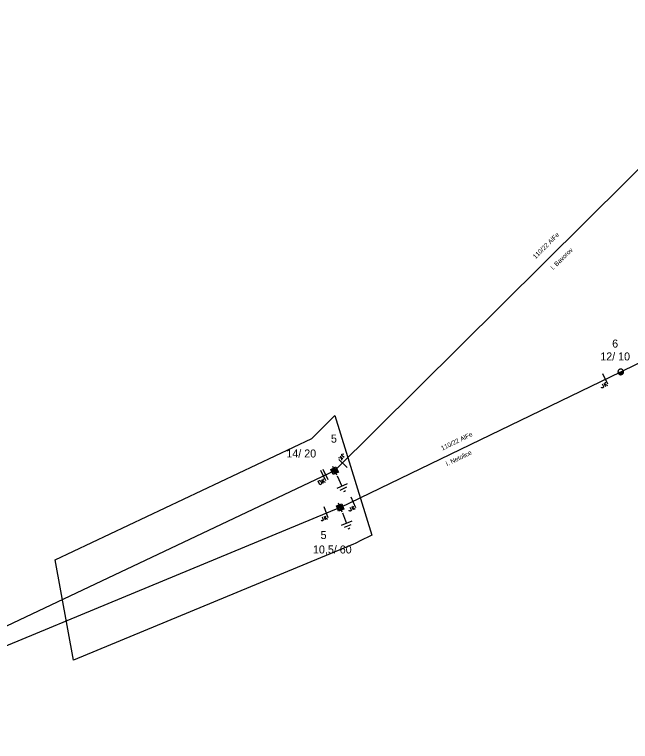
# Model space of a CAD drawing. Extents: x -788491 to -785797, y -1154753 to -1152002.
# Drawn here: x -787286.3 to -787151.7, y -1153654.2 to -1153495.3 of the extents above; entities that cross this region are included whole.
import ezdxf

# ---------------------------------------------------------------- set-up
doc = ezdxf.new("R2010")
doc.units = 0
for name, color, linetype in [('Vrstva 1', 7, 'Continuous'), ('Vrstva 13', 7, 'Continuous'), ('Vrstva 14', 7, 'Continuous'), ('Vrstva 15', 7, 'Continuous'), ('Vrstva 18', 7, 'Continuous'), ('Vrstva 2', 7, 'Continuous'), ('Vrstva 3', 7, 'Continuous'), ('Vrstva 35', 7, 'Continuous'), ('Vrstva 49', 7, 'Continuous')]:
    doc.layers.add(name, color=color, linetype=linetype)

# ---------------------------------------------------------------- blocks, each defined once
blk = doc.blocks.new('VN850')
at = {"layer": 'Vrstva 15'}
for points in [[(-0.56, 1.43), (-0.56, -1.07)], [(-0.01, 1.43), (-0.01, -1.07)], [(-2.09, -0.54), (-1.78, -0.54)], [(-2.09, -1.41), (-2.09, -0.54)], [(-1.78, -1.41), (-2.09, -1.41)], [(-1.78, -0.54), (-1.66, -0.6)], [(-1.67, -1.35), (-1.78, -1.41)], [(-1.59, -1.2), (-1.67, -1.35)], [(-1.66, -0.6), (-1.59, -0.75)], [(-1.59, -0.75), (-1.55, -0.96)], [(-1.55, -0.96), (-1.59, -1.2)], [(-1.26, -0.54), (-1.26, -1.41)], [(-0.85, -0.54), (-1.26, -1.09)], [(-1.13, -0.92), (-0.77, -1.41)]]:
    blk.add_lwpolyline(points, dxfattribs=at)
blk = doc.blocks.new('VN840')
at = {"layer": 'Vrstva 15'}
for points in [[(-0.01, 1.41), (-0.01, -1.09)], [(-1.51, -1.24), (-1.51, -1.15)], [(-1.48, -1.35), (-1.51, -1.24)], [(-1.33, -1.42), (-1.48, -1.35)], [(-1.27, -1.42), (-1.33, -1.42)], [(-1.13, -1.35), (-1.27, -1.42)], [(-1.09, -1.24), (-1.13, -1.35)], [(-1.09, -0.59), (-1.09, -1.24)], [(-0.68, -0.59), (-0.68, -1.42)], [(-0.68, -1.11), (-0.27, -0.59)], [(-0.54, -0.94), (-0.2, -1.42)]]:
    blk.add_lwpolyline(points, dxfattribs=at)
blk = doc.blocks.new('VN440')
at = {"layer": 'Vrstva 2'}
for points in [[(1.22, 0), (1.21, 0.13), (1.19, 0.25), (1.16, 0.38), (1.11, 0.5), (1.05, 0.61), (0.98, 0.72), (0.9, 0.82), (0.81, 0.91), (0.71, 0.99), (0.6, 1.06), (0.49, 1.12), (0.37, 1.16), (0.25, 1.2), (0.12, 1.22), (-0.01, 1.22), (-0.14, 1.22), (-0.26, 1.2), (-0.39, 1.16), (-0.51, 1.12), (-0.62, 1.06), (-0.73, 0.99), (-0.83, 0.91), (-0.92, 0.82), (-1, 0.72), (-1.07, 0.61), (-1.13, 0.5), (-1.18, 0.38), (-1.21, 0.25), (-1.23, 0.13), (-1.24, 0), (-1.23, -0.13), (-1.21, -0.26), (-1.18, -0.38), (-1.13, -0.5), (-1.07, -0.62), (-1, -0.73), (-0.92, -0.83), (-0.83, -0.92), (-0.73, -1), (-0.62, -1.07), (-0.51, -1.13), (-0.39, -1.17), (-0.26, -1.2), (-0.14, -1.23), (-0.01, -1.23), (0.12, -1.23), (0.25, -1.2), (0.37, -1.17), (0.49, -1.13), (0.6, -1.07), (0.71, -1), (0.81, -0.92), (0.9, -0.83), (0.98, -0.73), (1.05, -0.62), (1.11, -0.5), (1.16, -0.38), (1.19, -0.26), (1.21, -0.13), (1.22, 0)], [(-1.24, 0), (1.22, 0)], [(-1.18, -0.34), (1.1, -0.34)], [(-1.01, -0.63), (0.97, -0.63)], [(-0.74, -0.92), (0.68, -0.92)]]:
    blk.add_lwpolyline(points, dxfattribs=at)
blk = doc.blocks.new('VN810')
at = {"layer": 'Vrstva 14'}
for points in [[(0, -1.25), (0, -3.75)], [(1.25, -3.75), (-1.25, -3.75)], [(0.77, -4.37), (-0.8, -4.37)], [(0, -5), (-0.25, -5)], [(0.27, -5), (0, -5)]]:
    blk.add_lwpolyline(points, dxfattribs=at)
blk = doc.blocks.new('VN470')
at = {"layer": 'Vrstva 2'}
for points in [[(-1.23, 1.22), (1.23, 1.22)], [(-1.23, -1.23), (-1.23, 1.22)], [(-0.92, 0.9), (0.92, 0.9)], [(-0.92, -0.95), (-0.92, 0.9)], [(-0.61, 0.61), (0.61, 0.61)], [(-0.61, -0.62), (-0.61, 0.61)], [(-0.31, -0.27), (-0.31, 0.34)], [(-0.31, 0.34), (0.31, 0.34)], [(0, 1.22), (0, 1.97)], [(0.31, 0.34), (0.31, -0.27)], [(0.61, 0.61), (0.61, -0.62)], [(0.92, 0.9), (0.92, -0.95)], [(1.23, 1.22), (1.23, -1.23)], [(1.23, -1.23), (-1.23, -1.23)], [(0.92, -0.95), (-0.92, -0.95)], [(0.61, -0.62), (-0.61, -0.62)], [(0.31, -0.27), (-0.31, -0.27)], [(0, -1.23), (0, -1.98)]]:
    blk.add_lwpolyline(points, dxfattribs=at)

msp = doc.modelspace()

# ---------------------------------------------------------------- linework, layer by layer
at = {"layer": 'Vrstva 1'}
for points in [[(-787115.83, -1153495.28), (-787216.37, -1153594.98), (-787339.12, -1153653.04)], [(-787153.82, -1153573.38), (-787083.9, -1153539.18), (-787008.76, -1153502.68)], [(-787215.15, -1153603.03), (-787153.82, -1153573.38)], [(-787215.15, -1153603.03), (-787338.59, -1153654.16)]]:
    msp.add_lwpolyline(points, dxfattribs=at)
at = {"layer": 'Vrstva 35'}
msp.add_lwpolyline([(-787208.2, -1153609.1), (-787210.9, -1153610.4), (-787211.45, -1153610.67), (-787211.9, -1153610.88), (-787212.24, -1153611.02), (-787273.43, -1153636.36), (-787277.42, -1153614.45), (-787221.32, -1153587.92), (-787216.31, -1153582.95)], close=True, dxfattribs=at)

# ---------------------------------------------------------------- block references
at = {"layer": 'Vrstva 13'}
for name, p, xscale, yscale, rotation in [('VN440', (-787153.82, -1153573.38), 0.5, 0.5, 19.950088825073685), ('VN470', (-787216.37, -1153594.98), 0.49999999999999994, 0.5000000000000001, 25.251308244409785), ('VN470', (-787215.15, -1153603.03), 0.5, 0.49999999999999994, 19.950088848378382)]:
    msp.add_blockref(name, p, dxfattribs=dict(at, xscale=xscale, yscale=yscale, rotation=rotation))
at = {"layer": 'Vrstva 15'}
for p, rotation in [((-787216.37, -1153594.98), 25.414466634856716), ((-787215.15, -1153603.03), 21.997761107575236)]:
    msp.add_blockref('VN810', p, dxfattribs=dict(at, rotation=rotation))
at = {"layer": 'Vrstva 18'}
for name, p, rotation in [('VN840', (-787157.19, -1153575), 25.801452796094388), ('VN840', (-787214.66, -1153593.28), -135.19561667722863), ('VN850', (-787218.31, -1153595.9), 25.314225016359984), ('VN840', (-787212.25, -1153601.98), 22.85992221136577), ('VN840', (-787218.25, -1153604.16), 19.950088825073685)]:
    msp.add_blockref(name, p, dxfattribs=dict(at, rotation=rotation))

# ---------------------------------------------------------------- texts
at = {"layer": 'Vrstva 14'}
for s, p in [('6', (-787155.7, -1153568.07)), ('5', (-787217.17, -1153588.84)), ('5', (-787219.43, -1153609.9))]:
    msp.add_text(s, height=1.75, dxfattribs=at).set_placement(p)
at = {"layer": 'Vrstva 2'}
for rotation, p in [(44.797, (-787172.45, -1153548.75)), (25.801, (-787192.82, -1153590.59))]:
    msp.add_text('110/22 AlFe', height=1, rotation=rotation, dxfattribs=at).set_placement(p)
at = {"layer": 'Vrstva 3'}
for s, rotation, p in [('l. Bavorov', 44.797, (-787168.55, -1153551.15)), ('l. Netolice', 25.801, (-787191.74, -1153593.98))]:
    msp.add_text(s, height=1, rotation=rotation, dxfattribs=at).set_placement(p)
at = {"layer": 'Vrstva 49'}
for s, p in [('12/ 10', (-787158.3, -1153570.88)), ('14/ 20', (-787226.91, -1153592.09)), ('10,5/ 60', (-787221.1, -1153613.07))]:
    msp.add_text(s, height=1.75, dxfattribs=at).set_placement(p)

doc.saveas('drawing.dxf')
